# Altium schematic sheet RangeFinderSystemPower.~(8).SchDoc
size A; DocumentNumber: 6; SheetNumber: 6; SheetTotal: 6
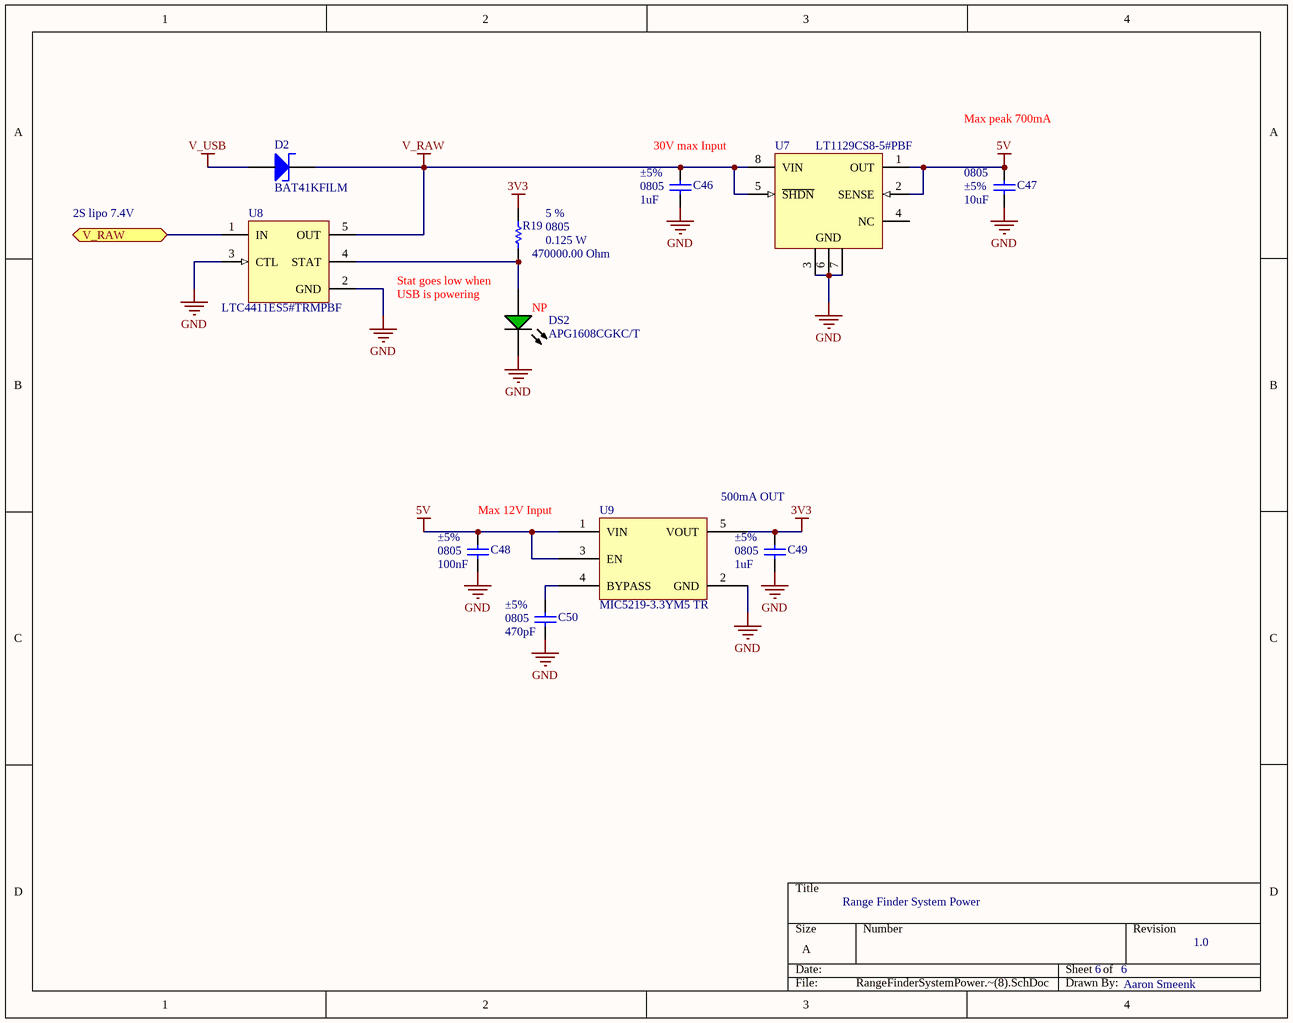
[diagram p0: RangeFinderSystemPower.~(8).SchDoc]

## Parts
C46  value 1uF  Tolerance: ±5%  Case-EIA: 0805  [CAPC0805(2012)100_M]  (hidden comment: CAP 1uF 6.3V 0805(2012))
C47  value 10uF  Case-EIA: 0805  Tolerance: ±5%  [CAPC0805(2012)145_M]  (hidden comment: CAP 10uF 6.3V 0805(2012))
C48  value 100nF  Tolerance: ±5%  Case-EIA: 0805  [CAPC0805(2012)100_L]  (hidden comment: CAP 100nF 6.3V 0805(2012))
C49  value 1uF  Tolerance: ±5%  Case-EIA: 0805  [CAPC0805(2012)100_M]  (hidden comment: CAP 1uF 6.3V 0805(2012))
C50  value 470pF  Case-EIA: 0805  Tolerance: ±5%  [CAPC0805(2012)100_L]  (hidden comment: CAP 470pF 6.3V 0805(2012))
D2  BAT41KFILM  [BAT41KFILM]
DS2  APG1608CGKC/T  [KING-LED0603-25-GREEN_V]
R19  value 470000.00 Ohm  Power: 0.125 W  Tolerance: 5 %  Case-EIA: 0805  [RESC0805(2012)_M]  (hidden comment: 470K 5% 0805(2012))
U7  LT1129CS8-5#PBF  [LT-S8-8_N]
U8  LTC4411ES5#TRMPBF  [LT-S5-5-TSOT-23_N]
U9  MIC5219-3.3YM5 TR

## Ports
V_RAW

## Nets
3V3: C49.2 R19.2 U9.5(VOUT)
5V: C47.2 C48.2 U7.1(OUT) U7.2(SENSE) U9.1(VIN) U9.3(EN)
GND: C46.1 C47.1 C48.1 C49.1 C50.1 DS2.2(K) U7.3(GND) U7.6(GND) U7.7(GND) U8.2(GND) U8.3(CTL) U9.2(GND)
V_RAW: C46.2 D2.1 U7.5(~{SHDN}) U7.8(VIN) U8.5(OUT)
V_USB: D2.2
V_RAW: U8.1(IN) ; port V_RAW  [a separate net that carries the same name]
NetC50_2: C50.2 U9.4(BYPASS)
NetDS2_1: DS2.1(A) R19.1 U8.4(STAT)

Not connected (* = marked no-connect by the designer): U7 4(NC)

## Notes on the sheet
- (near C46) 30V max Input
- Max peak 700mA
- 2S lipo 7.4V
- Stat goes low when
- USB is powering
- (near DS2) NP
- 500mA OUT
- (near C48) Max 12V Input
- Range Finder System Power
- 6
- 1.0
- Aaron Smeenk

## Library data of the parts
C46 C49 = CMP-1036-04730-1: CAP 1uF 6.3V ±5% 0805 (2012 Metric) Thickness 1mm SMD; Case-Metric: 2012
C47 = CMP-1036-04784-1: CAP 10uF 6.3V ±5% 0805 (2012 Metric) Thickness 1.45mm SMD; Case-Metric: 2012
C48 = CMP-1036-04390-1: CAP 100nF 6.3V ±5% 0805 (2012 Metric) Thickness 1mm SMD; Case-Metric: 2012
C50 = CMP-1036-02639-1: CAP 470pF 6.3V ±5% 0805 (2012 Metric) Thickness 1mm SMD; Case-Metric: 2012
D2 = BAT41KFILM: DIODE SCHOTTKY 100V 200MA SOD523; Current - Average Rectified (Io): 200mA (DC); Voltage - Forward (Vf) (Max) @ If: 1V @ 200mA; Speed: Small Signal =< 200mA (Io), Any Speed; Current - Reverse Leakage @ Vr: 100nA @ 50V; Capacitance @ Vr, F: 10pF @ 1V, 1MHz
DS2 = CMP-0239-00001-1: LED, SMT, 0603(1608), 0.25mm Thickness, Green; Forward Current: 30 mA; Reverse Voltage: 5 V; Power Dissipation: 78 mW; Packing: Reel
R19 = CMP-1013-00138-1: 470K 0.125W 5% 0805 (2012 Metric)  SMD; Case-Metric: 2012
U7 = CMP-0476-01544-1: Micropower Low Dropout Regulator with Shutdown, 4.15 to 30 V Vin, 5 V Vout, 8-pin SOIC (S8-8), 0 to 125 degC, Pb-Free; Manufacturer: Linear Technology; Dropout Voltage(V): 0.45; Discrete Pass Element: no; PSRR(dB): 64; Iout(mA): 700; Isupply(mA): 0.05; Vin Min(V): 4.15; Number of Outputs: 1; Output Voltage: 5 V; Vin Max(V): 30; Shutdown Current(uA): 16
U8 = CMP-0479-00414-1: Integrated Switch: Replaces Power Supply OR, 2.6 to 5.5 V Vin, 5-pin SOT23 (S5-5), -40 to 85 degC, Pb-Free, Mini Tape and Reel; Manufacturer: Linear Technology; Ideal Diode: Single, Internal, P-Channel
U9 = MIC5219-3.3YM5 TR: IC REG LDO 3.3V 0.5A SOT23-5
